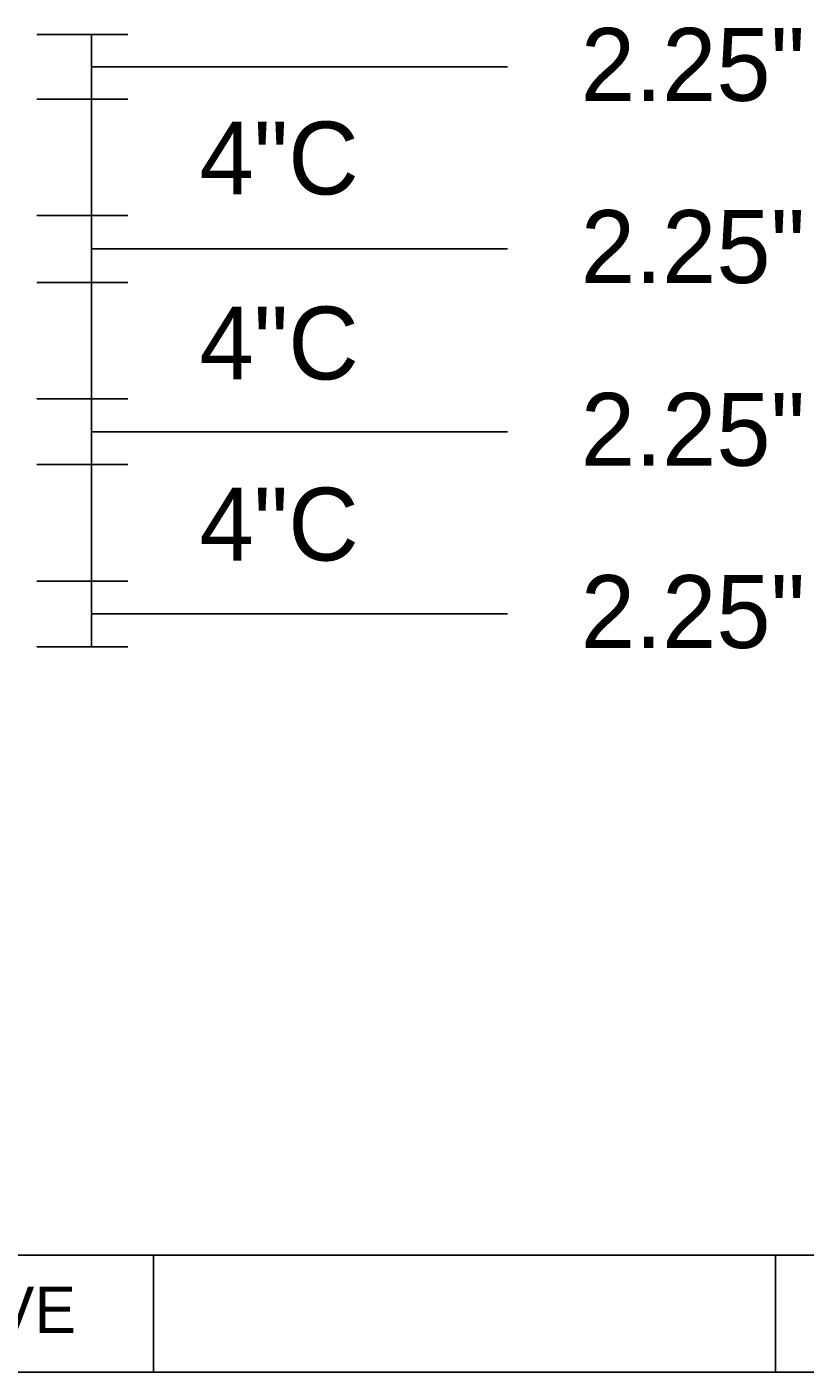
# Model space of a CAD drawing. Extents: x 17890628 to 17890754, y 17897693 to 17897992.
# Drawn here: x 17890720.624 to 17890722.848, y 17897894.166 to 17897898.011 of the extents above; entities that cross this region are included whole.
import ezdxf

# ---------------------------------------------------------------- set-up
doc = ezdxf.new("R2010")
doc.units = 0
for name, color, linetype in [('GSDims', 7, 'Continuous'), ('SheetLinesMisc2_dp', 7, 'Continuous'), ('TextMinor', 7, 'Continuous')]:
    doc.layers.add(name, color=color, linetype=linetype)

msp = doc.modelspace()

# ---------------------------------------------------------------- linework, layer by layer
at = {"layer": 'GSDims'}
for p, q in [((17890720.6522, 17897897.9895), (17890720.9126, 17897897.9895)), ((17890720.6522, 17897897.9895), (17890720.6522, 17897897.9895)), ((17890720.8085, 17897897.8053), (17890720.8085, 17897897.9895)), ((17890720.8085, 17897897.8974), (17890721.9976, 17897897.8974)), ((17890720.6522, 17897897.8053), (17890720.9126, 17897897.8053)), ((17890720.6522, 17897897.8053), (17890720.9126, 17897897.8053)), ((17890720.8085, 17897897.8053), (17890720.8085, 17897897.472)), ((17890720.6522, 17897897.472), (17890720.9126, 17897897.472)), ((17890720.6522, 17897897.472), (17890720.9126, 17897897.472)), ((17890720.8085, 17897897.2812), (17890720.8085, 17897897.472)), ((17890720.8085, 17897897.3766), (17890721.9976, 17897897.3766)), ((17890720.6522, 17897897.2812), (17890720.9126, 17897897.2812)), ((17890720.6522, 17897897.2812), (17890720.9126, 17897897.2812)), ((17890720.8085, 17897897.2812), (17890720.8085, 17897896.9479)), ((17890720.6522, 17897896.9479), (17890720.9126, 17897896.9479)), ((17890720.6522, 17897896.9479), (17890720.9126, 17897896.9479)), ((17890720.8085, 17897896.7604), (17890720.8085, 17897896.9479)), ((17890720.8085, 17897896.8541), (17890721.9976, 17897896.8541)), ((17890720.6522, 17897896.7604), (17890720.9126, 17897896.7604)), ((17890720.6522, 17897896.7604), (17890720.9126, 17897896.7604)), ((17890720.8085, 17897896.7604), (17890720.8085, 17897896.427)), ((17890720.6522, 17897896.427), (17890720.9126, 17897896.427)), ((17890720.6522, 17897896.427), (17890720.9126, 17897896.427)), ((17890720.8085, 17897896.2395), (17890720.8085, 17897896.427)), ((17890720.8085, 17897896.3333), (17890721.9976, 17897896.3333)), ((17890720.6522, 17897896.2395), (17890720.9126, 17897896.2395)), ((17890720.6522, 17897896.2395), (17890720.6522, 17897896.2395))]:
    msp.add_line(p, q, dxfattribs=at)
at = {"layer": 'SheetLinesMisc2_dp'}
for p, q in [((17890713.0553, 17897894.4997), (17890725.8465, 17897894.4997)), ((17890720.986, 17897894.4997), (17890720.986, 17897894.1659)), ((17890722.7637, 17897894.4997), (17890722.7637, 17897894.1659)), ((17890713.0553, 17897894.1659), (17890725.8466, 17897894.1659))]:
    msp.add_line(p, q, dxfattribs=at)

# ---------------------------------------------------------------- texts
at = {"layer": 'GSDims'}
for s, p in [('2.25"', (17890722.2073, 17897897.8)), ('4"C', (17890721.1173, 17897897.5324)), ('2.25"', (17890722.2073, 17897897.2792)), ('4"C', (17890721.1173, 17897897.0036)), ('2.25"', (17890722.2073, 17897896.7567)), ('4"C', (17890721.1173, 17897896.4859)), ('2.25"', (17890722.2073, 17897896.2358))]:
    msp.add_text(s, height=0.20833, rotation=360, dxfattribs=at).set_placement(p)
at = {"layer": 'TextMinor'}
msp.add_text('PHOTOMETRIC CURVE', height=0.132863, dxfattribs=at).set_placement((17890718.78, 17897894.2777))

doc.saveas('drawing.dxf')
